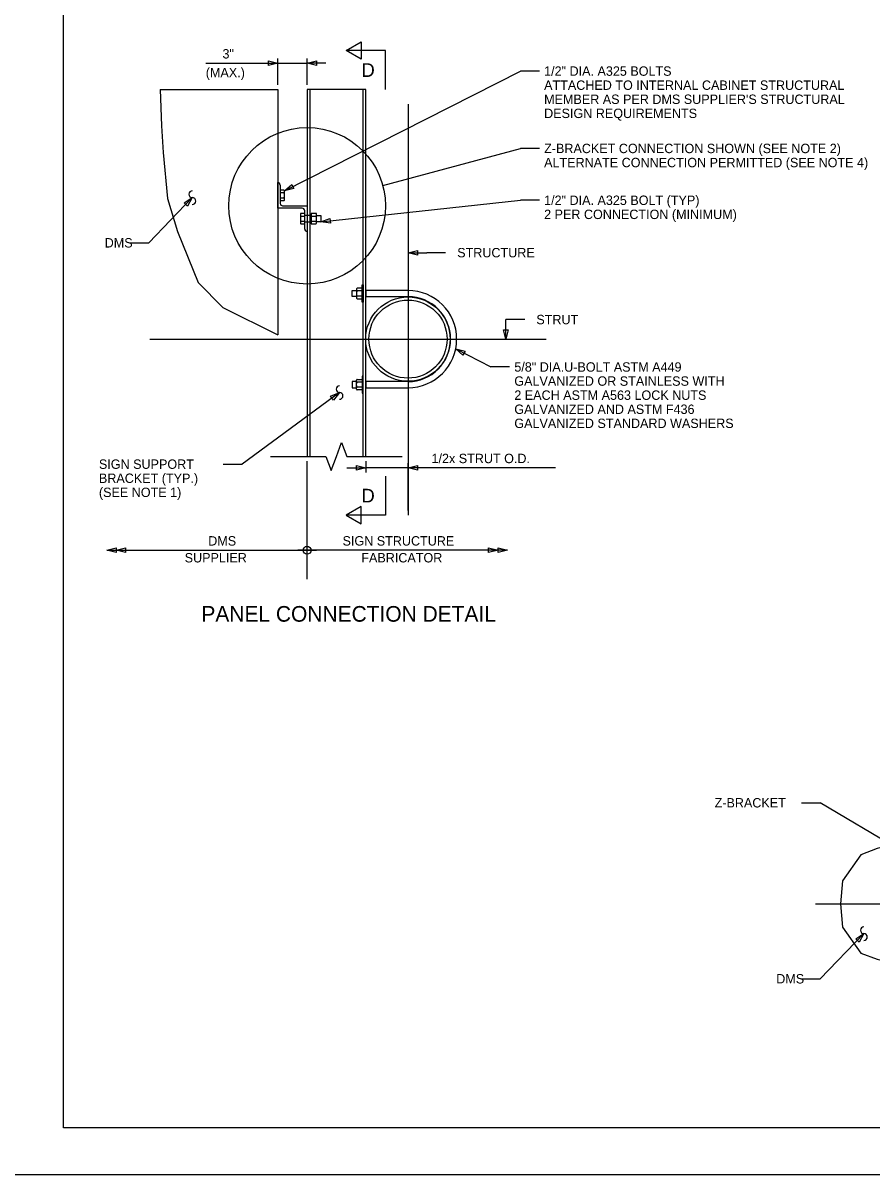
# Model space of a CAD drawing. Extents: x 3829340 to 3831660, y 499389 to 501171.
# Drawn here: x 3830208.1 to 3830479, y 499389.2 to 499757.1 of the extents above; entities that cross this region are included whole.
import ezdxf

# ---------------------------------------------------------------- set-up
doc = ezdxf.new("R2010")
doc.units = 0
for name, color, linetype in [('0-ANCHOR', 7, 'Continuous'), ('2', 7, 'Continuous'), ('CNTR', 7, 'Continuous'), ('Default', 7, 'Continuous'), ('DIM TXT', 7, 'Continuous'), ('PLT-BNDY', 7, 'Continuous'), ('sign', 7, 'Continuous'), ('structure', 7, 'Continuous')]:
    doc.layers.add(name, color=color, linetype=linetype)

msp = doc.modelspace()

# ---------------------------------------------------------------- linework, layer by layer
at = {"layer": '0-ANCHOR'}
for p, q in [((3830291.32, 499703.72), (3830290.15, 499703.72)), ((3830290.15, 499703.72), (3830290.15, 499700.4)), ((3830291.32, 499702.89), (3830290.15, 499702.89)), ((3830291.32, 499701.23), (3830290.15, 499701.23)), ((3830291.51, 499700.59), (3830291.51, 499703.53)), ((3830290.15, 499700.4), (3830291.32, 499700.4)), ((3830296.59, 499696.11), (3830296.59, 499693.17)), ((3830297.96, 499696.3), (3830296.78, 499696.3)), ((3830296.78, 499695.47), (3830297.96, 499695.47)), ((3830296.78, 499693.81), (3830297.96, 499693.81)), ((3830297.96, 499692.98), (3830297.96, 499696.3)), ((3830299.99, 499695.62), (3830297.96, 499695.62)), ((3830297.96, 499693.66), (3830299.99, 499693.66)), ((3830301.56, 499696.3), (3830299.99, 499696.3)), ((3830299.99, 499696.3), (3830299.99, 499692.98)), ((3830299.99, 499693.66), (3830299.99, 499695.62)), ((3830299.99, 499695.47), (3830301.56, 499695.47)), ((3830299.99, 499693.81), (3830301.56, 499693.81)), ((3830301.75, 499693.17), (3830301.75, 499696.11)), ((3830301.75, 499695.62), (3830303.1, 499695.62)), ((3830303.1, 499693.66), (3830301.75, 499693.66)), ((3830303.1, 499695.62), (3830303.1, 499693.66)), ((3830296.78, 499692.98), (3830297.96, 499692.98)), ((3830299.99, 499692.98), (3830301.56, 499692.98))]:
    msp.add_line(p, q, dxfattribs=at)
for centre, start, end in [((3830291.32, 499703.53), 360, 90), ((3830291.32, 499703.08), 270, 0), ((3830291.32, 499701.04), 360, 90), ((3830291.32, 499700.59), 270, 0), ((3830296.78, 499696.11), 90, 180), ((3830296.78, 499695.66), 180, 270), ((3830296.78, 499693.62), 90, 180), ((3830301.56, 499696.11), 360, 90), ((3830301.56, 499695.66), 270, 0), ((3830301.56, 499693.62), 360, 90), ((3830296.78, 499693.17), 180, 270), ((3830301.56, 499693.17), 270, 0)]:
    msp.add_arc(centre, 0.187, start, end, dxfattribs=at)
for centre, major_axis, start_param, end_param in [((3830291.32, 499702.37), (0, 0.518), 4.712389, 6.283185), ((3830291.32, 499701.75), (0, -0.518), 0, 1.570796), ((3830296.78, 499694.95), (0, 0.518), 0, 1.570796), ((3830296.78, 499694.33), (0, -0.518), 4.712389, 6.283185), ((3830301.56, 499694.95), (0, 0.518), 4.712389, 6.283185), ((3830301.56, 499694.33), (0, -0.518), 0, 1.570796)]:
    msp.add_ellipse(centre, major_axis=major_axis, ratio=0.362172, start_param=start_param, end_param=end_param, dxfattribs=at)
at = {"layer": '2'}
for p, q in [((3830220.96, 499404.19), (3830220.96, 499968.19)), ((3831006.96, 499404.19), (3830220.96, 499404.19))]:
    msp.add_line(p, q, dxfattribs=at)
at = {"layer": 'CNTR'}
for p, q in [((3830330.93, 499731.16), (3830330.93, 499599.92)), ((3830248.49, 499656.16), (3830375.05, 499656.16)), ((3830460.93, 499475.75), (3830568.91, 499475.75))]:
    msp.add_line(p, q, dxfattribs=at)
at = {"layer": 'Default'}
for p, q in [((3830311.21, 499748.35), (3830315.97, 499751.1)), ((3830315.97, 499751.1), (3830315.97, 499745.6)), ((3830315.97, 499745.6), (3830311.21, 499748.35)), ((3830315.97, 499602.67), (3830311.21, 499599.92)), ((3830315.97, 499597.17), (3830315.97, 499602.67)), ((3830311.21, 499599.92), (3830315.97, 499597.17))]:
    msp.add_line(p, q, dxfattribs=at)
at = {"layer": 'DIM TXT'}
for p, q in [((3830289.36, 499737.35), (3830289.36, 499745.79)), ((3830298.74, 499737.35), (3830298.74, 499745.79)), ((3830323.71, 499748.35), (3830311.21, 499748.35)), ((3830323.71, 499735.85), (3830323.71, 499748.35)), ((3830266.39, 499744.29), (3830289.36, 499744.29)), ((3830289.36, 499744.29), (3830298.74, 499744.29)), ((3830291.51, 499703.53), (3830366.87, 499741.77)), ((3830304.74, 499744.29), (3830298.74, 499744.29)), ((3830372.87, 499741.77), (3830366.87, 499741.77)), ((3830322.88, 499705.23), (3830366.87, 499717.06)), ((3830372.87, 499717.06), (3830366.87, 499717.06)), ((3830262.1, 499701.34), (3830248.17, 499686.92)), ((3830303.1, 499693.66), (3830366.87, 499700.51)), ((3830372.87, 499700.51), (3830366.87, 499700.51)), ((3830242.17, 499686.92), (3830248.17, 499686.92)), ((3830330.93, 499683.71), (3830336.93, 499683.71)), ((3830342.93, 499683.71), (3830336.93, 499683.71)), ((3830362.18, 499656.16), (3830362.18, 499662.41)), ((3830368.18, 499662.41), (3830362.18, 499662.41)), ((3830346.15, 499653.06), (3830357.36, 499647.26)), ((3830363.36, 499647.26), (3830357.36, 499647.26)), ((3830309.1, 499639.08), (3830277.96, 499616.22)), ((3830308.1, 499618.67), (3830309.76, 499623.18)), ((3830309.76, 499623.18), (3830311.43, 499618.67)), ((3830287.08, 499618.67), (3830304.76, 499618.67)), ((3830298.74, 499579.52), (3830298.74, 499617.17)), ((3830304.76, 499618.67), (3830306.43, 499614.16)), ((3830306.43, 499614.16), (3830308.1, 499618.67)), ((3830311.43, 499618.67), (3830329.11, 499618.67)), ((3830317.46, 499617.17), (3830317.46, 499613.54)), ((3830330.93, 499601.42), (3830330.93, 499616.54)), ((3830271.96, 499616.22), (3830277.96, 499616.22)), ((3830311.46, 499615.04), (3830317.46, 499615.04)), ((3830330.93, 499615.04), (3830317.46, 499615.04)), ((3830378.05, 499615.04), (3830330.93, 499615.04)), ((3830323.71, 499612.42), (3830323.71, 499599.92)), ((3830323.71, 499599.92), (3830311.21, 499599.92)), ((3830234.81, 499588.72), (3830298.74, 499588.72)), ((3830237.81, 499588.72), (3830301.74, 499588.72)), ((3830359.67, 499588.72), (3830295.74, 499588.72)), ((3830362.67, 499588.72), (3830298.74, 499588.72)), ((3830456.5, 499508.06), (3830462.5, 499508.06)), ((3830489.61, 499491.89), (3830462.5, 499508.06)), ((3830476.42, 499466.26), (3830462.5, 499451.85)), ((3830456.5, 499451.85), (3830462.5, 499451.85))]:
    msp.add_line(p, q, dxfattribs=at)
for points in [[(3830286.36, 499745.04), (3830289.36, 499744.29), (3830286.36, 499743.54)], [(3830301.74, 499743.54), (3830298.74, 499744.29), (3830301.74, 499745.04)], [(3830294.53, 499704.22), (3830291.51, 499703.53), (3830293.85, 499705.56)], [(3830259.48, 499699.7), (3830262.1, 499701.34), (3830260.56, 499698.66)], [(3830306.16, 499693.24), (3830303.1, 499693.66), (3830306, 499694.73)], [(3830333.93, 499682.96), (3830330.93, 499683.71), (3830333.93, 499684.46)], [(3830362.93, 499659.16), (3830362.18, 499656.16), (3830361.43, 499659.16)], [(3830348.47, 499651.01), (3830346.15, 499653.06), (3830349.16, 499652.34)], [(3830306.24, 499637.91), (3830309.1, 499639.08), (3830307.13, 499636.7)], [(3830314.46, 499615.79), (3830317.46, 499615.04), (3830314.46, 499614.29)], [(3830333.93, 499614.29), (3830330.93, 499615.04), (3830333.93, 499615.79)], [(3830237.81, 499587.97), (3830234.81, 499588.72), (3830237.81, 499589.47)], [(3830240.81, 499587.97), (3830237.81, 499588.72), (3830240.81, 499589.47)], [(3830356.67, 499589.47), (3830359.67, 499588.72), (3830356.67, 499587.97)], [(3830359.67, 499589.47), (3830362.67, 499588.72), (3830359.67, 499587.97)], [(3830473.8, 499464.63), (3830476.42, 499466.26), (3830474.88, 499463.59)]]:
    msp.add_lwpolyline(points, close=True, dxfattribs=at)
for centre, radius in [((3830298.74, 499698.74), 25), ((3830298.74, 499588.72), 1.25)]:
    msp.add_circle(centre, radius, dxfattribs=at)
for centre, start, end in [((3830262.1, 499702.41), 90, 270), ((3830262.1, 499700.26), 270, 90), ((3830309.1, 499640.16), 90, 270), ((3830309.1, 499638.01), 270, 90), ((3830476.42, 499467.34), 90, 270), ((3830476.42, 499465.19), 270, 90)]:
    msp.add_arc(centre, 1.08, start, end, dxfattribs=at)
at = {"layer": 'PLT-BNDY'}
msp.add_lwpolyline([(3830180.96, 499983.19), (3831021.96, 499983.19), (3831021.96, 499389.19), (3830180.96, 499389.19)], close=True, dxfattribs=at)
at = {"layer": 'sign'}
for p, q in [((3830251.87, 499735.85), (3830289.36, 499735.85)), ((3830251.87, 499735.85), (3830252.21, 499724.23)), ((3830289.36, 499735.85), (3830289.36, 499657.57)), ((3830252.21, 499724.23), (3830252.78, 499715.73)), ((3830252.78, 499715.73), (3830254.16, 499701.12)), ((3830289.36, 499697.96), (3830289.36, 499706.16)), ((3830290.15, 499705.38), (3830290.15, 499699.52)), ((3830254.16, 499701.12), (3830257.39, 499690.52)), ((3830297.18, 499697.96), (3830289.36, 499697.96)), ((3830290.93, 499698.74), (3830298.74, 499698.74)), ((3830298.74, 499698.74), (3830298.74, 499690.54)), ((3830297.96, 499691.32), (3830297.96, 499697.18)), ((3830257.39, 499690.52), (3830263.99, 499674.22)), ((3830263.99, 499674.22), (3830271.83, 499666.22)), ((3830313.15, 499669.74), (3830313.15, 499671.69)), ((3830313.15, 499671.69), (3830314.5, 499671.69)), ((3830314.5, 499672.19), (3830314.5, 499669.24)), ((3830316.25, 499672.38), (3830314.68, 499672.38)), ((3830316.25, 499667.98), (3830316.25, 499673.45)), ((3830316.25, 499673.45), (3830316.64, 499673.45)), ((3830316.25, 499669.05), (3830316.25, 499672.38)), ((3830316.64, 499673.45), (3830316.64, 499667.98)), ((3830330.93, 499671.69), (3830317.46, 499671.69)), ((3830317.46, 499671.69), (3830317.46, 499669.74)), ((3830314.5, 499669.74), (3830313.15, 499669.74)), ((3830316.25, 499671.54), (3830314.68, 499671.54)), ((3830316.25, 499669.88), (3830314.68, 499669.88)), ((3830314.68, 499669.05), (3830316.25, 499669.05)), ((3830316.64, 499667.98), (3830316.25, 499667.98)), ((3830317.46, 499669.74), (3830330.93, 499669.74)), ((3830271.83, 499666.22), (3830289.36, 499657.57)), ((3830314.5, 499642.59), (3830313.15, 499642.59)), ((3830313.15, 499642.59), (3830313.15, 499640.64)), ((3830314.5, 499640.14), (3830314.5, 499643.09)), ((3830314.68, 499643.27), (3830316.25, 499643.27)), ((3830316.25, 499642.44), (3830314.68, 499642.44)), ((3830316.64, 499644.35), (3830316.25, 499644.35)), ((3830316.25, 499644.35), (3830316.25, 499638.88)), ((3830316.25, 499643.27), (3830316.25, 499639.95)), ((3830316.64, 499638.88), (3830316.64, 499644.35)), ((3830330.93, 499642.59), (3830317.46, 499642.59)), ((3830317.46, 499642.59), (3830317.46, 499640.64)), ((3830313.15, 499640.64), (3830314.5, 499640.64)), ((3830316.25, 499640.78), (3830314.68, 499640.78)), ((3830316.25, 499639.95), (3830314.68, 499639.95)), ((3830316.25, 499638.88), (3830316.64, 499638.88)), ((3830317.46, 499640.64), (3830330.93, 499640.64))]:
    msp.add_line(p, q, dxfattribs=at)
for points in [[(3830485.16, 499494.5), (3830480.65, 499493.43), (3830475.45, 499491.46), (3830469.58, 499483.17), (3830468.95, 499475.75)], [(3830468.95, 499475.75), (3830469.58, 499468.34), (3830475.45, 499460.05), (3830480.65, 499458.08), (3830485.16, 499457.01)]]:
    msp.add_lwpolyline(points, dxfattribs=at)
for centre, radius, start, end in [((3830289.36, 499705.38), 0.781, 0, 90), ((3830290.93, 499699.52), 0.781, 180, 270), ((3830297.18, 499697.18), 0.781, 0, 90), ((3830298.74, 499691.32), 0.781, 180, 270), ((3830314.68, 499672.19), 0.187, 90, 180), ((3830314.68, 499671.73), 0.187, 180, 270), ((3830330.93, 499656.16), 15.53, 270, 90), ((3830314.68, 499669.7), 0.187, 90, 180), ((3830314.68, 499669.24), 0.187, 180, 270), ((3830330.93, 499656.16), 13.57, 270, 90), ((3830314.68, 499643.09), 0.187, 90, 180), ((3830314.68, 499642.63), 0.187, 180, 270), ((3830314.68, 499640.6), 0.187, 90, 180), ((3830314.68, 499640.14), 0.187, 180, 270)]:
    msp.add_arc(centre, radius, start, end, dxfattribs=at)
for centre, major_axis, start_param, end_param in [((3830314.68, 499671.03), (0, 0.518), 0, 1.570796), ((3830314.68, 499670.4), (0, -0.518), 4.712389, 6.283185), ((3830314.68, 499641.93), (0, 0.518), 0, 1.570796), ((3830314.68, 499641.3), (0, -0.518), 4.712389, 6.283185)]:
    msp.add_ellipse(centre, major_axis=major_axis, ratio=0.362172, start_param=start_param, end_param=end_param, dxfattribs=at)
at = {"layer": 'structure'}
for p, q in [((3830317.46, 499735.85), (3830298.74, 499735.85)), ((3830298.74, 499735.85), (3830298.74, 499618.67)), ((3830316.64, 499735.85), (3830299.55, 499735.85)), ((3830299.55, 499735.85), (3830299.55, 499618.67)), ((3830316.64, 499618.67), (3830316.64, 499735.85)), ((3830317.46, 499618.67), (3830317.46, 499735.85))]:
    msp.add_line(p, q, dxfattribs=at)
for radius in [13.48, 12.47]:
    msp.add_circle((3830330.93, 499656.16), radius, dxfattribs=at)

# ---------------------------------------------------------------- texts
at = {"layer": 'Default'}
msp.add_text('PANEL CONNECTION DETAIL', height=4.9999, dxfattribs=at).set_placement((3830264.99, 499565.9))
at = {"layer": 'DIM TXT'}
for s, height, p in [('3"', 3, (3830271.72, 499745.79)), ('(MAX.)', 3, (3830266.39, 499739.79)), ('D', 4.37, (3830316.1, 499739.91)), ('1/2" DIA. A325 BOLTS', 2.9999, (3830374.37, 499740.27)), ('ATTACHED TO INTERNAL CABINET STRUCTURAL', 2.9999, (3830374.37, 499735.77)), ("MEMBER AS PER DMS SUPPLIER'S STRUCTURAL", 2.9999, (3830374.37, 499731.27)), ('DESIGN REQUIREMENTS', 2.9999, (3830374.37, 499726.77)), ('Z-BRACKET CONNECTION SHOWN (SEE NOTE 2)', 2.9999, (3830374.37, 499715.56)), ('ALTERNATE CONNECTION PERMITTED (SEE NOTE 4)', 2.9999, (3830374.37, 499711.06)), ('1/2" DIA. A325 BOLT (TYP)', 2.9999, (3830374.37, 499699.01)), ('2 PER CONNECTION (MINIMUM)', 2.9999, (3830374.37, 499694.51)), ('DMS', 3, (3830234.13, 499685.42)), ('  STRUCTURE', 2.9999, (3830344.41, 499682.27)), ('  STRUT', 3, (3830369.66, 499660.91)), ('5/8" DIA.U-BOLT ASTM A449', 2.9999, (3830364.86, 499645.76)), ('GALVANIZED OR STAINLESS WITH', 2.9999, (3830364.86, 499641.26)), ('2 EACH ASTM A563 LOCK NUTS', 2.9999, (3830364.86, 499636.76)), ('GALVANIZED AND ASTM F436', 2.9999, (3830364.86, 499632.26)), ('GALVANIZED STANDARD WASHERS', 2.9999, (3830364.86, 499627.76)), ('SIGN SUPPORT', 2.9999, (3830232.29, 499614.72)), ('1/2x STRUT O.D.', 2.9999, (3830338.43, 499616.54)), ('BRACKET (TYP.)', 2.9999, (3830232.29, 499610.22)), ('(SEE NOTE 1)', 2.9999, (3830232.29, 499605.72)), ('D', 4.37, (3830316.1, 499603.98)), ('DMS', 3, (3830267.17, 499590.22)), ('SIGN STRUCTURE', 2.9999, (3830310.04, 499590.22)), ('SUPPLIER', 3, (3830259.66, 499584.83)), ('FABRICATOR', 3, (3830316.03, 499584.83)), ('Z-BRACKET', 3, (3830428.78, 499506.56)), ('DMS', 3, (3830448.45, 499450.35))]:
    msp.add_text(s, height=height, dxfattribs=at).set_placement(p)

doc.saveas('drawing.dxf')
